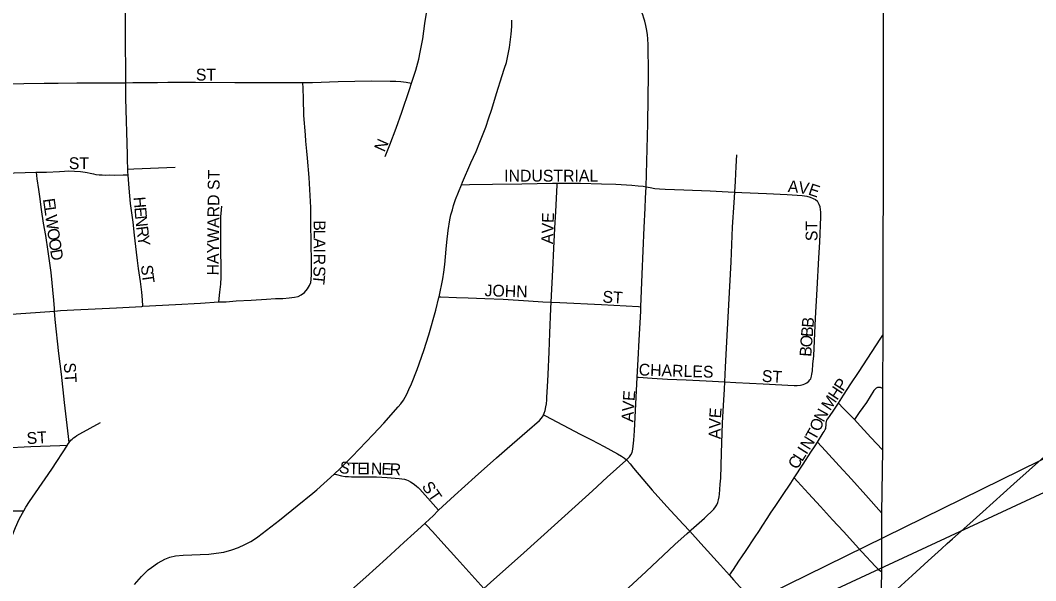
# Model space of a CAD drawing. Extents: x 1772825 to 1773716, y 1138558 to 1139032.
# Drawn here: x 1773356.3 to 1773372.55, y 1138885.5 to 1138894.47 of the extents above; entities that cross this region are included whole.
import ezdxf

# ---------------------------------------------------------------- set-up
doc = ezdxf.new("R2010")
doc.units = 0
for name, color, linetype in [('GM_X_City_Street', 7, 'Continuous'), ('GM_X_City_Street_Text', 7, 'Continuous'), ('GM_X_Corporation', 7, 'Continuous'), ('GM_X_State_Route', 7, 'Continuous'), ('SH_Text', 7, 'Continuous')]:
    doc.layers.add(name, color=color, linetype=linetype)

msp = doc.modelspace()

# ---------------------------------------------------------------- linework, layer by layer
at = {"layer": 'GM_X_City_Street'}
for points in [[(1773362.562, 1138893.462), (1773362.631, 1138893.666), (1773362.679, 1138893.844), (1773362.702, 1138893.958), (1773362.743, 1138894.167), (1773362.778, 1138894.416), (1773362.801, 1138894.579), (1773362.809, 1138894.694), (1773362.816, 1138894.79), (1773362.814, 1138894.877), (1773362.806, 1138894.976), (1773362.793, 1138895.115), (1773362.774, 1138895.258), (1773362.733, 1138895.628), (1773362.699, 1138895.912), (1773362.684, 1138896.08), (1773362.677, 1138896.195), (1773362.666, 1138896.382), (1773362.664, 1138896.476), (1773362.669, 1138896.54), (1773362.676, 1138896.587), (1773362.693, 1138896.667)], [(1773366.318, 1138891.804), (1773366.328, 1138892.208), (1773366.344, 1138892.813), (1773366.356, 1138893.608), (1773366.352, 1138894.08), (1773366.344, 1138894.165), (1773366.34, 1138894.239), (1773366.325, 1138894.327), (1773366.314, 1138894.384), (1773366.295, 1138894.449), (1773366.281, 1138894.502), (1773366.263, 1138894.551), (1773366.236, 1138894.616), (1773366.208, 1138894.68), (1773366.163, 1138894.758), (1773366.014, 1138895.001), (1773365.702, 1138895.467), (1773365.659, 1138895.533), (1773365.631, 1138895.585), (1773365.592, 1138895.674)], [(1773357.989, 1138893.467), (1773357.989, 1138893.481), (1773357.988, 1138894.27), (1773357.985, 1138894.618), (1773357.983, 1138894.879), (1773357.983, 1138895.027)], [(1773363.365, 1138891.836), (1773363.381, 1138891.876), (1773363.514, 1138892.184), (1773363.599, 1138892.369), (1773363.657, 1138892.515), (1773363.75, 1138892.758), (1773363.801, 1138892.904), (1773363.841, 1138893.028), (1773363.929, 1138893.312), (1773363.95, 1138893.382), (1773363.987, 1138893.499), (1773364.011, 1138893.569), (1773364.051, 1138893.699), (1773364.081, 1138893.792), (1773364.102, 1138893.873), (1773364.129, 1138894.032), (1773364.157, 1138894.244), (1773364.167, 1138894.367), (1773364.168, 1138894.467)], [(1773352.815, 1138893.437), (1773352.92, 1138893.438), (1773353.711, 1138893.446), (1773353.971, 1138893.446), (1773354.294, 1138893.448), (1773354.467, 1138893.448), (1773354.715, 1138893.449), (1773354.839, 1138893.448), (1773354.962, 1138893.447), (1773355.194, 1138893.45), (1773355.615, 1138893.451), (1773355.813, 1138893.449), (1773356.035, 1138893.451), (1773356.686, 1138893.458), (1773356.91, 1138893.459), (1773357.207, 1138893.464), (1773357.405, 1138893.464), (1773357.552, 1138893.464), (1773357.989, 1138893.467)], [(1773357.989, 1138893.467), (1773358.105, 1138893.468), (1773358.241, 1138893.468), (1773358.501, 1138893.473), (1773358.662, 1138893.474), (1773359.106, 1138893.475), (1773359.737, 1138893.468), (1773359.998, 1138893.47), (1773360.184, 1138893.47), (1773360.358, 1138893.47), (1773360.632, 1138893.472), (1773360.78, 1138893.471), (1773360.823, 1138893.472)], [(1773358.023, 1138892.085), (1773358.019, 1138892.234), (1773358.017, 1138892.321), (1773357.992, 1138893.214), (1773357.989, 1138893.467)], [(1773360.823, 1138893.472), (1773360.978, 1138893.473), (1773361.392, 1138893.484), (1773361.925, 1138893.497), (1773362.222, 1138893.493), (1773362.312, 1138893.49), (1773362.391, 1138893.484), (1773362.479, 1138893.474), (1773362.562, 1138893.462)], [(1773360.85, 1138890.114), (1773360.899, 1138890.172), (1773360.932, 1138890.226), (1773360.95, 1138890.27), (1773360.96, 1138890.319), (1773360.964, 1138890.402), (1773360.964, 1138890.533), (1773360.964, 1138890.665), (1773360.959, 1138890.835), (1773360.952, 1138891.285), (1773360.95, 1138891.469), (1773360.927, 1138891.95), (1773360.9, 1138892.263), (1773360.888, 1138892.373), (1773360.884, 1138892.423), (1773360.874, 1138892.534), (1773360.865, 1138892.632), (1773360.841, 1138892.942), (1773360.833, 1138893.215), (1773360.827, 1138893.377), (1773360.823, 1138893.472)], [(1773362.142, 1138892.285), (1773362.216, 1138892.473), (1773362.316, 1138892.74), (1773362.41, 1138892.994), (1773362.532, 1138893.358), (1773362.562, 1138893.462)], [(1773367.74, 1138891.716), (1773367.749, 1138891.893), (1773367.76, 1138892.125), (1773367.77, 1138892.315)], [(1773356.56, 1138892.035), (1773356.72, 1138892.039), (1773356.929, 1138892.048), (1773357.009, 1138892.053), (1773357.074, 1138892.057), (1773357.171, 1138892.053), (1773357.267, 1138892.045), (1773357.303, 1138892.041), (1773357.339, 1138892.036), (1773357.374, 1138892.03), (1773357.419, 1138892.021), (1773357.475, 1138892.009), (1773357.511, 1138892.001), (1773357.564, 1138891.996), (1773357.613, 1138891.994), (1773357.669, 1138891.99), (1773357.728, 1138891.992), (1773357.813, 1138891.99), (1773357.948, 1138891.992), (1773358.029, 1138891.993)], [(1773358.023, 1138892.085), (1773358.118, 1138892.089), (1773358.782, 1138892.115)], [(1773358.029, 1138891.993), (1773358.025, 1138892.037), (1773358.023, 1138892.085)], [(1773351.947, 1138891.885), (1773353.671, 1138891.937), (1773355.271, 1138891.993), (1773355.68, 1138892.008), (1773356.553, 1138892.035), (1773356.56, 1138892.035)], [(1773356.852, 1138889.814), (1773356.85, 1138889.854), (1773356.841, 1138889.99), (1773356.795, 1138890.434), (1773356.75, 1138890.766), (1773356.709, 1138891.024), (1773356.672, 1138891.219), (1773356.641, 1138891.44), (1773356.615, 1138891.648), (1773356.6, 1138891.759), (1773356.575, 1138891.931), (1773356.56, 1138892.035)], [(1773358.266, 1138889.892), (1773358.257, 1138889.993), (1773358.247, 1138890.117), (1773358.224, 1138890.29), (1773358.194, 1138890.498), (1773358.179, 1138890.621), (1773358.163, 1138890.756), (1773358.132, 1138891.027), (1773358.107, 1138891.237), (1773358.068, 1138891.533), (1773358.044, 1138891.778), (1773358.029, 1138891.989), (1773358.029, 1138891.993)], [(1773363.004, 1138890.045), (1773363.062, 1138890.33), (1773363.078, 1138890.439), (1773363.094, 1138890.56), (1773363.116, 1138890.805), (1773363.127, 1138890.916), (1773363.149, 1138891.101), (1773363.178, 1138891.274), (1773363.195, 1138891.355), (1773363.217, 1138891.432), (1773363.237, 1138891.505), (1773363.266, 1138891.599), (1773363.365, 1138891.836)], [(1773363.365, 1138891.836), (1773363.489, 1138891.838), (1773363.861, 1138891.843), (1773364.33, 1138891.85), (1773364.821, 1138891.858), (1773364.896, 1138891.858)], [(1773364.797, 1138889.957), (1773364.823, 1138890.474), (1773364.843, 1138890.817), (1773364.858, 1138891.14), (1773364.872, 1138891.409), (1773364.895, 1138891.829), (1773364.896, 1138891.858)], [(1773364.896, 1138891.858), (1773365.268, 1138891.858), (1773365.605, 1138891.852), (1773365.835, 1138891.842), (1773366.09, 1138891.83), (1773366.192, 1138891.82), (1773366.268, 1138891.812), (1773366.318, 1138891.804)], [(1773366.234, 1138889.885), (1773366.256, 1138890.407), (1773366.289, 1138891.149), (1773366.304, 1138891.462), (1773366.31, 1138891.621), (1773366.318, 1138891.804)], [(1773366.318, 1138891.804), (1773366.384, 1138891.791), (1773366.455, 1138891.776), (1773366.531, 1138891.768), (1773366.621, 1138891.764), (1773366.922, 1138891.754), (1773367.345, 1138891.739), (1773367.633, 1138891.722), (1773367.74, 1138891.716)], [(1773367.578, 1138888.683), (1773367.59, 1138888.918), (1773367.616, 1138889.423), (1773367.677, 1138890.603), (1773367.701, 1138891.157), (1773367.728, 1138891.549), (1773367.74, 1138891.716)], [(1773367.74, 1138891.716), (1773367.847, 1138891.71), (1773368.245, 1138891.696), (1773368.575, 1138891.678), (1773368.816, 1138891.661), (1773368.888, 1138891.65), (1773368.944, 1138891.635), (1773368.992, 1138891.617), (1773369.028, 1138891.599), (1773369.062, 1138891.571)], [(1773368.922, 1138888.696), (1773368.938, 1138888.715), (1773368.951, 1138888.733), (1773368.958, 1138888.75), (1773368.965, 1138888.772), (1773368.972, 1138888.808), (1773368.979, 1138888.861), (1773368.988, 1138888.965), (1773368.999, 1138889.098), (1773369.028, 1138889.699), (1773369.055, 1138890.165), (1773369.083, 1138890.665), (1773369.097, 1138890.919), (1773369.112, 1138891.324), (1773369.112, 1138891.395), (1773369.11, 1138891.441), (1773369.102, 1138891.484), (1773369.089, 1138891.521), (1773369.062, 1138891.571)], [(1773359.48, 1138889.96), (1773359.496, 1138890.115), (1773359.51, 1138890.247), (1773359.517, 1138890.358), (1773359.517, 1138890.506), (1773359.513, 1138890.79), (1773359.51, 1138891.012), (1773359.511, 1138891.161), (1773359.514, 1138891.322), (1773359.522, 1138891.433), (1773359.528, 1138891.494)], [(1773359.48, 1138889.96), (1773359.598, 1138889.964), (1773359.759, 1138889.976), (1773359.998, 1138889.99), (1773360.243, 1138890.004), (1773360.387, 1138890.014), (1773360.503, 1138890.018), (1773360.608, 1138890.028), (1773360.692, 1138890.037), (1773360.751, 1138890.049), (1773360.799, 1138890.072), (1773360.85, 1138890.114)], [(1773358.266, 1138889.892), (1773358.789, 1138889.92), (1773359.186, 1138889.94), (1773359.48, 1138889.96)], [(1773361.324, 1138887.207), (1773361.423, 1138887.297), (1773361.614, 1138887.49), (1773361.95, 1138887.839), (1773362.118, 1138888.022), (1773362.348, 1138888.281), (1773362.394, 1138888.332), (1773362.436, 1138888.389), (1773362.487, 1138888.485), (1773362.521, 1138888.562), (1773362.562, 1138888.65), (1773362.652, 1138888.881), (1773362.763, 1138889.184), (1773362.84, 1138889.433), (1773362.952, 1138889.827), (1773363.001, 1138890.032), (1773363.004, 1138890.045)], [(1773363.004, 1138890.045), (1773363.035, 1138890.043), (1773363.282, 1138890.034), (1773363.472, 1138890.026), (1773363.735, 1138890.016), (1773364.029, 1138890.003), (1773364.433, 1138889.979), (1773364.664, 1138889.965), (1773364.797, 1138889.957)], [(1773364.676, 1138888.156), (1773364.688, 1138888.18), (1773364.702, 1138888.223), (1773364.715, 1138888.284), (1773364.721, 1138888.332), (1773364.729, 1138888.393), (1773364.731, 1138888.44), (1773364.742, 1138888.601), (1773364.749, 1138888.8), (1773364.766, 1138889.163), (1773364.779, 1138889.459), (1773364.794, 1138889.855), (1773364.797, 1138889.957)], [(1773364.797, 1138889.957), (1773364.937, 1138889.952), (1773365.604, 1138889.919), (1773366.196, 1138889.887), (1773366.234, 1138889.885)], [(1773353.94, 1138889.625), (1773354.08, 1138889.633), (1773355.026, 1138889.689), (1773355.373, 1138889.71), (1773356.235, 1138889.773), (1773356.621, 1138889.796), (1773356.852, 1138889.814)], [(1773356.852, 1138889.814), (1773356.944, 1138889.822), (1773357.161, 1138889.833), (1773357.841, 1138889.866), (1773358.246, 1138889.89), (1773358.266, 1138889.892)], [(1773357.084, 1138887.712), (1773357.074, 1138887.808), (1773357.042, 1138888.08), (1773357.008, 1138888.351), (1773356.961, 1138888.808), (1773356.922, 1138889.138), (1773356.861, 1138889.681), (1773356.852, 1138889.814)], [(1773366.176, 1138888.759), (1773366.189, 1138889.038), (1773366.206, 1138889.352), (1773366.231, 1138889.815), (1773366.234, 1138889.885)], [(1773369.396, 1138888.342), (1773369.476, 1138888.471), (1773369.595, 1138888.652), (1773369.717, 1138888.833), (1773370.074, 1138889.383), (1773370.104, 1138889.429)], [(1773366.003, 1138887.433), (1773366.052, 1138887.485), (1773366.072, 1138887.514), (1773366.092, 1138887.553), (1773366.107, 1138887.606), (1773366.111, 1138887.656), (1773366.119, 1138887.752), (1773366.131, 1138887.898), (1773366.176, 1138888.759)], [(1773366.176, 1138888.759), (1773366.197, 1138888.758), (1773366.413, 1138888.744), (1773366.661, 1138888.728), (1773366.96, 1138888.715), (1773367.278, 1138888.7), (1773367.578, 1138888.683)], [(1773367.015, 1138886.295), (1773367.036, 1138886.315), (1773367.252, 1138886.505), (1773367.4, 1138886.649), (1773367.426, 1138886.683), (1773367.448, 1138886.717), (1773367.463, 1138886.753), (1773367.475, 1138886.796), (1773367.487, 1138886.846), (1773367.493, 1138886.886), (1773367.5, 1138886.959), (1773367.505, 1138887.048), (1773367.511, 1138887.143), (1773367.524, 1138887.541), (1773367.541, 1138888.026), (1773367.557, 1138888.303), (1773367.571, 1138888.564), (1773367.578, 1138888.683)], [(1773367.578, 1138888.683), (1773367.755, 1138888.673), (1773368.19, 1138888.649), (1773368.688, 1138888.623), (1773368.734, 1138888.623), (1773368.787, 1138888.628), (1773368.831, 1138888.639), (1773368.859, 1138888.649), (1773368.892, 1138888.668), (1773368.922, 1138888.696)], [(1773370.101, 1138888.577), (1773370.088, 1138888.584), (1773370.079, 1138888.588), (1773370.068, 1138888.592), (1773370.055, 1138888.595), (1773370.044, 1138888.595), (1773370.031, 1138888.593), (1773370.02, 1138888.591), (1773370.009, 1138888.585), (1773370, 1138888.58), (1773369.989, 1138888.571), (1773369.977, 1138888.559), (1773369.964, 1138888.543), (1773369.847, 1138888.351), (1773369.729, 1138888.191), (1773369.708, 1138888.16), (1773369.651, 1138888.078)], [(1773369.058, 1138887.719), (1773369.153, 1138887.868), (1773369.167, 1138887.89), (1773369.184, 1138887.919), (1773369.191, 1138887.939), (1773369.196, 1138887.959), (1773369.199, 1138887.982), (1773369.2, 1138888.022), (1773369.204, 1138888.046), (1773369.21, 1138888.069), (1773369.226, 1138888.093), (1773369.263, 1138888.146), (1773369.31, 1138888.214), (1773369.396, 1138888.342)], [(1773369.651, 1138888.078), (1773369.57, 1138888.162), (1773369.473, 1138888.262), (1773369.396, 1138888.342)], [(1773357.084, 1138887.712), (1773357.085, 1138887.714), (1773357.114, 1138887.748), (1773357.134, 1138887.768), (1773357.154, 1138887.785), (1773357.18, 1138887.804), (1773357.208, 1138887.823), (1773357.253, 1138887.851), (1773357.587, 1138888.034)], [(1773362.996, 1138886.633), (1773363.251, 1138886.864), (1773363.583, 1138887.164), (1773363.921, 1138887.467), (1773364.096, 1138887.615), (1773364.416, 1138887.895), (1773364.612, 1138888.065), (1773364.643, 1138888.102), (1773364.668, 1138888.138), (1773364.676, 1138888.156)], [(1773364.676, 1138888.156), (1773364.709, 1138888.138), (1773365.264, 1138887.848), (1773365.445, 1138887.754), (1773365.646, 1138887.649), (1773365.862, 1138887.533), (1773365.925, 1138887.496), (1773365.974, 1138887.461), (1773366.003, 1138887.433)], [(1773370.102, 1138887.593), (1773369.915, 1138887.795), (1773369.696, 1138888.032), (1773369.651, 1138888.078)], [(1773354.2, 1138887.512), (1773354.301, 1138887.52), (1773354.511, 1138887.537), (1773354.598, 1138887.543), (1773354.709, 1138887.552), (1773355.069, 1138887.575), (1773355.23, 1138887.581), (1773355.565, 1138887.597), (1773355.675, 1138887.604), (1773356.048, 1138887.625), (1773356.469, 1138887.648), (1773356.936, 1138887.665), (1773357.057, 1138887.669)], [(1773356.358, 1138886.619), (1773356.393, 1138886.681), (1773356.452, 1138886.771), (1773356.544, 1138886.91), (1773356.806, 1138887.288), (1773357.057, 1138887.669)], [(1773357.057, 1138887.669), (1773357.06, 1138887.675), (1773357.084, 1138887.712)], [(1773368.686, 1138887.147), (1773368.829, 1138887.365), (1773368.954, 1138887.556), (1773369.021, 1138887.661), (1773369.058, 1138887.719)], [(1773370.086, 1138886.589), (1773369.833, 1138886.872), (1773369.603, 1138887.124), (1773369.405, 1138887.34), (1773369.187, 1138887.578), (1773369.058, 1138887.719)], [(1773363.722, 1138885.38), (1773363.83, 1138885.476), (1773364.361, 1138885.95), (1773364.853, 1138886.389), (1773365.459, 1138886.94), (1773365.697, 1138887.158), (1773365.994, 1138887.425), (1773366.003, 1138887.433)], [(1773366.003, 1138887.433), (1773366.012, 1138887.425), (1773366.061, 1138887.37), (1773366.115, 1138887.303), (1773366.263, 1138887.128), (1773366.415, 1138886.952), (1773366.65, 1138886.689), (1773366.91, 1138886.409), (1773367.015, 1138886.295)], [(1773358.131, 1138885.44), (1773358.241, 1138885.571), (1773358.313, 1138885.641), (1773358.351, 1138885.674), (1773358.401, 1138885.714), (1773358.501, 1138885.783), (1773358.568, 1138885.822), (1773358.618, 1138885.847), (1773358.696, 1138885.881), (1773358.787, 1138885.901), (1773358.908, 1138885.909), (1773359.32, 1138885.929), (1773359.439, 1138885.941), (1773359.562, 1138885.961), (1773359.69, 1138885.998), (1773359.794, 1138886.033), (1773359.894, 1138886.079), (1773359.993, 1138886.131), (1773360.05, 1138886.166), (1773360.102, 1138886.203), (1773360.45, 1138886.469), (1773360.735, 1138886.702), (1773360.982, 1138886.904), (1773361.049, 1138886.957), (1773361.324, 1138887.207)], [(1773361.324, 1138887.207), (1773361.363, 1138887.199), (1773361.444, 1138887.182), (1773361.503, 1138887.171), (1773361.553, 1138887.167), (1773361.603, 1138887.166), (1773362.005, 1138887.161), (1773362.174, 1138887.152), (1773362.364, 1138887.139), (1773362.406, 1138887.134), (1773362.45, 1138887.125), (1773362.481, 1138887.114), (1773362.509, 1138887.104), (1773362.548, 1138887.084), (1773362.574, 1138887.069), (1773362.61, 1138887.043), (1773362.645, 1138887.016), (1773362.672, 1138886.992), (1773362.696, 1138886.966), (1773362.869, 1138886.775), (1773362.996, 1138886.633)], [(1773367.651, 1138885.589), (1773367.715, 1138885.683), (1773367.802, 1138885.814), (1773367.862, 1138885.902), (1773367.908, 1138885.972), (1773368.063, 1138886.205), (1773368.119, 1138886.29), (1773368.185, 1138886.393), (1773368.253, 1138886.495), (1773368.321, 1138886.597), (1773368.382, 1138886.689), (1773368.498, 1138886.864), (1773368.631, 1138887.064), (1773368.686, 1138887.147)], [(1773368.686, 1138887.147), (1773368.74, 1138887.087), (1773368.914, 1138886.898), (1773369.106, 1138886.69), (1773369.303, 1138886.475), (1773369.475, 1138886.289), (1773369.768, 1138885.966), (1773369.988, 1138885.727), (1773370.041, 1138885.676), (1773370.083, 1138885.649)], [(1773354.307, 1138886.573), (1773354.606, 1138886.61), (1773354.679, 1138886.62), (1773354.775, 1138886.631), (1773354.882, 1138886.641), (1773354.954, 1138886.649), (1773355.053, 1138886.655), (1773355.164, 1138886.654), (1773355.301, 1138886.646), (1773355.436, 1138886.637), (1773355.845, 1138886.621), (1773356.242, 1138886.619), (1773356.358, 1138886.619)], [(1773355.846, 1138885.291), (1773355.946, 1138885.582), (1773356.029, 1138885.835), (1773356.101, 1138886.031), (1773356.162, 1138886.191), (1773356.225, 1138886.352), (1773356.287, 1138886.489), (1773356.337, 1138886.583), (1773356.358, 1138886.619)], [(1773362.777, 1138886.417), (1773362.857, 1138886.49), (1773362.907, 1138886.535), (1773362.996, 1138886.633)], [(1773361.562, 1138885.318), (1773361.83, 1138885.559), (1773362.161, 1138885.856), (1773362.442, 1138886.111), (1773362.608, 1138886.262), (1773362.777, 1138886.417)], [(1773363.722, 1138885.38), (1773363.29, 1138885.859), (1773363.032, 1138886.142), (1773362.901, 1138886.289), (1773362.805, 1138886.388), (1773362.777, 1138886.417)], [(1773364.766, 1138884.234), (1773364.996, 1138884.444), (1773365.417, 1138884.826), (1773365.967, 1138885.326), (1773366.317, 1138885.649), (1773366.776, 1138886.082), (1773366.972, 1138886.259), (1773367.015, 1138886.295)], [(1773367.015, 1138886.295), (1773367.195, 1138886.098), (1773367.506, 1138885.75), (1773367.651, 1138885.589)], [(1773367.651, 1138885.589), (1773367.716, 1138885.517), (1773368.018, 1138885.181), (1773368.343, 1138884.83), (1773368.714, 1138884.428), (1773368.903, 1138884.224), (1773368.967, 1138884.155)]]:
    msp.add_lwpolyline(points, dxfattribs=at)
at = {"layer": 'GM_X_Corporation'}
msp.add_lwpolyline([(1773370.116, 1138897.078), (1773370.104, 1138889.429), (1773370.101, 1138888.577), (1773370.102, 1138887.593), (1773370.086, 1138886.589), (1773370.083, 1138885.649), (1773370.076, 1138885.13), (1773369.903, 1138879.906), (1773370.536, 1138880.118), (1773370.519, 1138879.27), (1773370.439, 1138876.984), (1773371.686, 1138876.964), (1773372.091, 1138876.959), (1773372.157, 1138876.95), (1773372.207, 1138876.932), (1773372.257, 1138876.903), (1773372.474, 1138877.945), (1773376.152, 1138877.801), (1773376.238, 1138877.332), (1773376.247, 1138875.752)], dxfattribs=at)
at = {"layer": 'GM_X_State_Route'}
for points in [[(1773371.222, 1138886.173), (1773371.449, 1138886.375), (1773371.705, 1138886.602), (1773372.202, 1138887.053), (1773372.695, 1138887.491)], [(1773370.076, 1138885.13), (1773370.339, 1138885.371), (1773370.577, 1138885.588), (1773370.831, 1138885.82), (1773371.044, 1138886.013), (1773371.138, 1138886.098), (1773371.222, 1138886.173)]]:
    msp.add_lwpolyline(points, dxfattribs=at)
at = {"layer": 'SH_Text'}
msp.add_lwpolyline([(1773543.413, 1138971.185), (1773351.996, 1138877.306), (1773543.413, 1138966.239)], close=True, dxfattribs=at)

# ---------------------------------------------------------------- texts
at = {"layer": 'GM_X_City_Street_Text'}
for s, height, rotation, p in [('ST', 0.1894, 0, (1773359.112, 1138893.502)), ('N', 0.189, 66.0262, (1773362.13, 1138892.347)), ('ST', 0.1894, 0, (1773357.079, 1138892.085)), ('HAYWARD ST', 0.1894, 89.3903, (1773359.477, 1138890.384)), ('INDUSTRIAL', 0.1894, 0, (1773364.046, 1138891.885)), ('A', 0.189, 355.6466, (1773368.581, 1138891.719)), ('V', 0.189, 351.0228, (1773368.744, 1138891.706)), ('E', 0.189, 341.4873, (1773368.9, 1138891.682)), ('E', 0.189, 277.9756, (1773356.664, 1138891.605)), ('H', 0.189, 274.7709, (1773358.115, 1138891.636)), ('L', 0.189, 278.0001, (1773356.683, 1138891.472)), ('E', 0.189, 274.7903, (1773358.128, 1138891.47)), ('W', 0.189, 277.9779, (1773356.701, 1138891.34)), ('N', 0.189, 275.7737, (1773358.14, 1138891.333)), ('B', 0.189, 269.7814, (1773360.998, 1138891.267)), ('AVE', 0.1894, 88.0186, (1773364.827, 1138890.884)), ('ST', 0.1894, 90, (1773369.06, 1138890.933)), ('O', 0.189, 277.9986, (1773356.731, 1138891.126)), ('R', 0.189, 277.0689, (1773358.157, 1138891.163)), ('L', 0.189, 269.769, (1773360.997, 1138891.117)), ('O', 0.189, 278.193, (1773356.755, 1138890.96)), ('Y', 0.189, 277.1445, (1773358.176, 1138891.014)), ('A', 0.189, 269.7595, (1773360.997, 1138890.983)), ('D', 0.189, 279.7518, (1773356.779, 1138890.789)), ('I', 0.189, 269.7919, (1773360.996, 1138890.817)), ('R', 0.189, 269.7814, (1773360.996, 1138890.733)), ('S', 0.189, 275.7188, (1773358.232, 1138890.545)), ('S', 0.189, 269.7814, (1773360.995, 1138890.533)), ('T', 0.189, 277.9251, (1773358.246, 1138890.404)), ('T', 0.189, 264.3084, (1773360.995, 1138890.405)), ('JOHN', 0.1894, 358.4097, (1773363.73, 1138890.052)), ('ST', 0.1894, 356.4254, (1773365.615, 1138889.952)), ('B', 0.189, 85.4853, (1773368.995, 1138889.544)), ('B', 0.189, 85.4784, (1773368.983, 1138889.395)), ('O', 0.189, 85.5141, (1773368.97, 1138889.229)), ('B', 0.189, 86.0632, (1773368.96, 1138889.08)), ('ST', 0.1894, 273.5746, (1773356.998, 1138888.985)), ('CHARLES', 0.1894, 358.2133, (1773366.197, 1138888.785)), ('ST', 0.1894, 356.4254, (1773368.165, 1138888.685)), ('P', 0.189, 57.5037, (1773369.47, 1138888.52)), ('AVE', 0.1894, 86.0494, (1773366.11, 1138888.035)), ('H', 0.189, 56.3532, (1773369.375, 1138888.377)), ('M', 0.189, 55.8301, (1773369.262, 1138888.21)), ('E', 0.189, 85.8171, (1773367.515, 1138888.096)), ('N', 0.189, 61.0197, (1773369.157, 1138888.026)), ('V', 0.189, 88.2729, (1773367.51, 1138887.931)), ('O', 0.189, 70.2113, (1773369.103, 1138887.877)), ('ST', 0.1894, 3.5738, (1773356.41, 1138887.685)), ('A', 0.189, 89.8907, (1773367.51, 1138887.766)), ('T', 0.189, 60.7345, (1773369.024, 1138887.73)), ('N', 0.189, 58.0098, (1773368.931, 1138887.58)), ('L', 0.189, 57.4662, (1773368.813, 1138887.395)), ('I', 0.189, 57.4884, (1773368.885, 1138887.508)), ('S', 0.189, 348.9741, (1773361.393, 1138887.233)), ('T', 0.189, 359.3044, (1773361.561, 1138887.204)), ('E', 0.189, 359.9322, (1773361.697, 1138887.202)), ('I', 0.189, 359.9563, (1773361.83, 1138887.202)), ('N', 0.189, 359.0164, (1773361.912, 1138887.202)), ('E', 0.189, 357.5947, (1773362.078, 1138887.199)), ('R', 0.189, 357.5221, (1773362.211, 1138887.193)), ('C', 0.189, 57.4618, (1773368.732, 1138887.269)), ('ST', 0.1894, 304.7645, (1773362.72, 1138887.009))]:
    msp.add_text(s, height=height, rotation=rotation, dxfattribs=at).set_placement(p)

doc.saveas('drawing.dxf')
